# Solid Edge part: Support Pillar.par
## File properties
Author: Dan
Template: metric part.par
Last saved by: Dan
Revision: 4
Application: Solid Edge
Material: Steel
Face Style: Steel
Fill Style: ANSI32(Steel)
Virtual Style: Machined steel
Coef. of Thermal Exp: 1.3e-05
Thermal Conductivity: 32.0
Specific Heat: 481.0
Modulus of Elasticity: 199947953000.0
Poisson's Ratio: 0.29
Yield Stress: 262000766.0
Ultimate Stress: 358527364.0
Elongation: 0.0
Density: 7833.000 kg/m^3
Accuracy: 0.990
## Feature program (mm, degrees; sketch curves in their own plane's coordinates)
sketch for "unnamed Protrusion 1" plane through (0, 0, 0) normal (0, 0, 1) x-axis (1, 0, 0)
extrude "unnamed Protrusion 1" add finite 86 along +normal
sketch for "Hole_1" plane through (0, 0, 86) normal (0, 0, 1) x-axis (0, 1, 0)
hole "Hole_1" diameter 8 finite  VBottomAngle = 118 deg
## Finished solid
Body 1: solid body, 5 faces, 4 edges, 1 vertex.
  Faces by surface: cylinder 2, plane 2, cone 1
  Edges by curve: circle 4
Bounding box of the edges (mm): 70.000 x 70.000 x 86.000, from (-35, -35, 0) to (35, 35, 86).
Cylindrical faces by radius (mm): R3.3235 x1, R35 x1
Conical faces (half-angle, radius in mm at the cone's reference point): 59 deg R3.3235 x1
Planar faces by outward normal: +z 1, -z 1
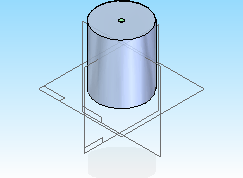
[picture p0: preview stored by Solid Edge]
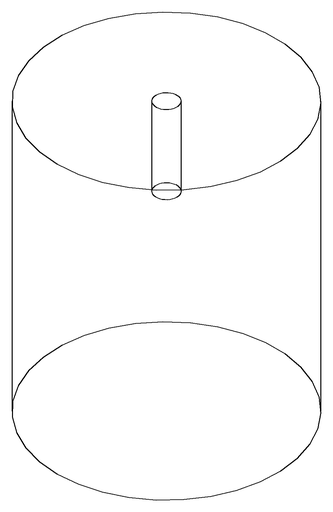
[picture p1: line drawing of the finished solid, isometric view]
